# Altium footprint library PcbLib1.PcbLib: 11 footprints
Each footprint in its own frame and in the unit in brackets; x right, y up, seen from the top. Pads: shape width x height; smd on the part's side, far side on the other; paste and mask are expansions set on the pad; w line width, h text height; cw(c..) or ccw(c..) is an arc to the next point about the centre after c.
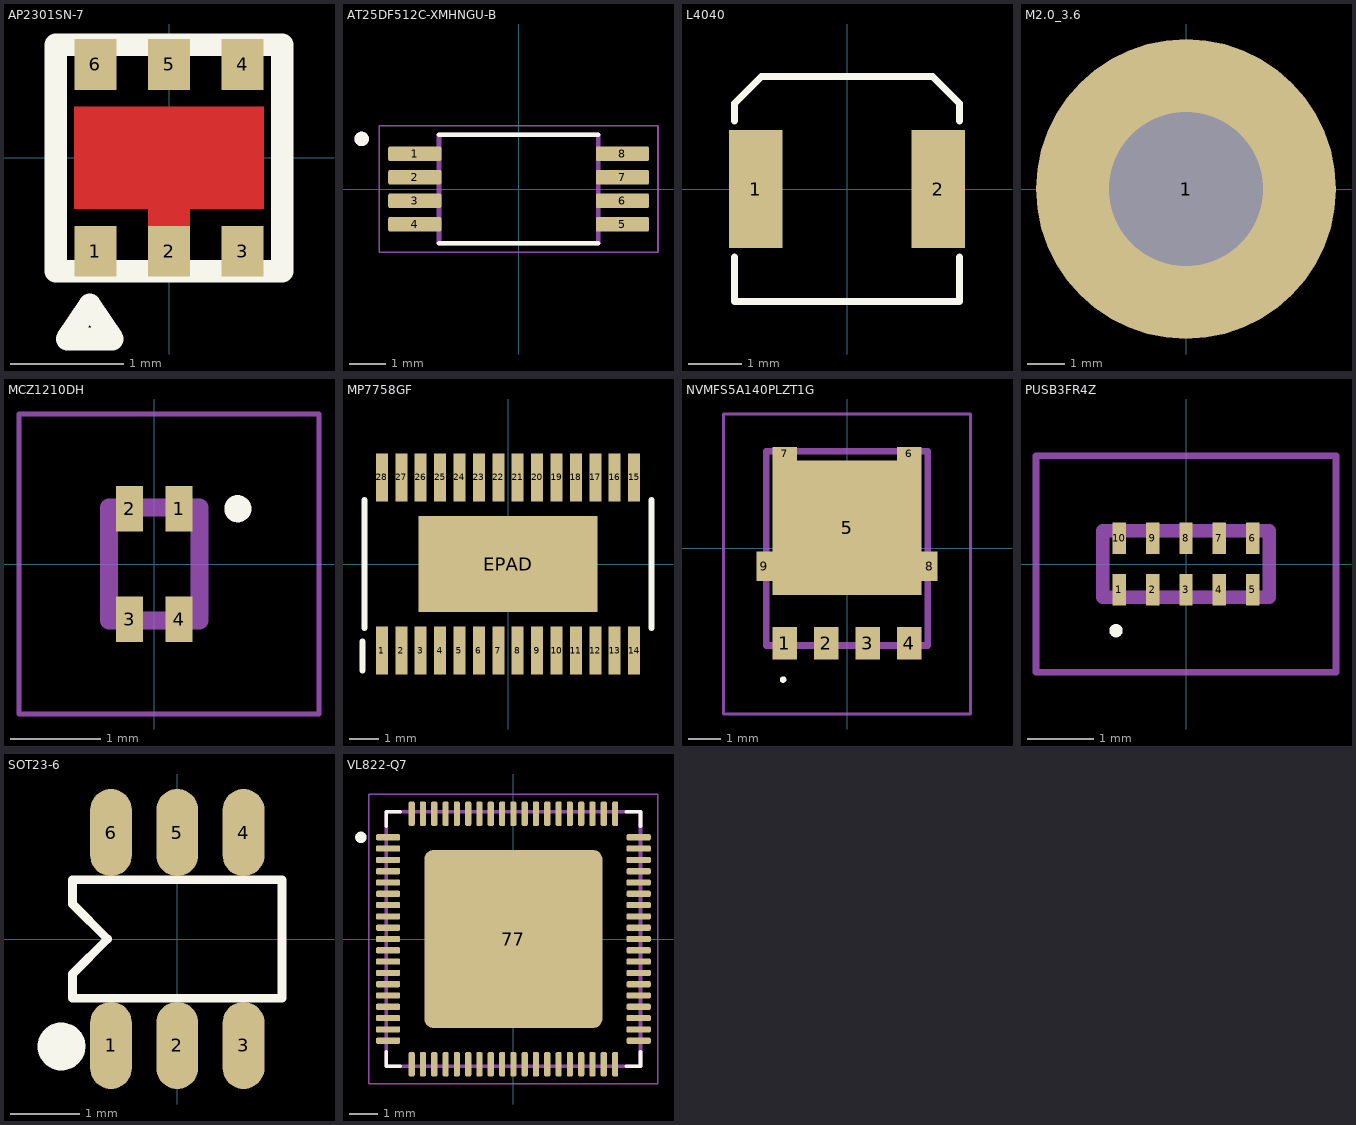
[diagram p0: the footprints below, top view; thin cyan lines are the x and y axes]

## AP2301SN-7 [mm] "Power Switch ICs - Power Distribution 2.0A SGL CH 70mOhm 2.5A 2.7 to 5.5V"
pads (6):
  rect 0.37x0.45 smd: 1(-0.65,-0.825) 2(0,-0.825) 3(0.65,-0.825) 4(0.65,0.825) 5(0,0.825) 6(-0.65,0.825)
Top Layer:
  region: -0.835,0.45 -0.835,-0.45 -0.185,-0.45 -0.185,-0.825 0.185,-0.825 0.185,-0.45 0.835,-0.45 0.835,0.45
Top Overlay:
  lines w0.2: -1,-1 -1,1 1,1 1,-1 -1,-1 ; -0.9,-1.6 -0.7,-1.3 -0.5,-1.6 -0.9,-1.6
3D body "U-DFN2020-6.stp": height 0.61, standoff 0.01, extent -1,-1 1,1

## AT25DF512C-XMHNGU-B [mm] "NOR Flash 512Kb, 1.65V, 85Mhz Serial Flash"
pads (8):
  rrect25% 1.47x0.41 smd: 1(-2.87,0.975) 2(-2.87,0.325) 3(-2.87,-0.325) 4(-2.87,-0.975) 5(2.87,-0.975) 6(2.87,-0.325) 7(2.87,0.325) 8(2.87,0.975)
Top Overlay:
  circle w0.2: c-4.34,1.385 r0.1
  lines w0.127: -2.2,-1.5 2.2,-1.5 ; -2.2,1.5 2.2,1.5
Mechanical 13:
  circle w0.2: c-4.34,1.385 r0.1
  lines w0.127: -2.2,-1.5 -2.2,1.5 2.2,1.5 2.2,-1.5 -2.2,-1.5
Mechanical 15:
  lines w0.05: -3.855,-1.75 -3.855,1.75 3.855,1.75 3.855,-1.75 -3.855,-1.75
3D body "step_temp.STEP": height 1.2, standoff 0, extent -3.2,-1.5 3.2,1.5

## L4040 [mm]
height 2.108
pads (2):
  rect 1x2.2 smd: 1(-1.7,0) 2(1.7,0)
Top Overlay:
  lines w0.127: -2.1,-1.27 -2.1,-2.1 2.1,-2.1 2.1,-1.27 ; -2.1,1.27 -2.1,1.6 -1.6,2.1 1.6,2.1 2.1,1.6 2.1,1.27
Top Assembly:
  text "L2" at 0.444,0.374 h0.64
3D body "L_XND4040TK.STEP": height 1.8, standoff 0, extent -2,-2 2,2

## M2.0_3.6 [mm]
pads (1):
  round 8 hole 4.1: 1(0,0)

## MCZ1210DH [mm]
pads (4):
  rect 0.3x0.5 smd: 1(0.275,0.613) 2(-0.275,0.613) 3(-0.275,-0.613) 4(0.275,-0.613)
Top Overlay:
  circle w0.2: c0.925,0.613 r0.05
Mechanical 13:
  lines w0.2: -0.5,-0.625 -0.5,0.625 0.5,0.625 0.5,-0.625 -0.5,-0.625
Mechanical 15:
  lines w0.05: -1.5,-1.663 -1.5,1.663 1.825,1.663 1.825,-1.663 -1.5,-1.663
3D body "MCZ1210DH500L2TA0G.stp": height 0.7, standoff 0, extent -0.5,-0.833 0.5,0.833

## MP7758GF [mm] "TSSOP-28"
pads (29):
  rect 0.4x1.6 smd: 1(-4.225,-2.9) 2(-3.575,-2.9) 3(-2.925,-2.9) 4(-2.275,-2.9) 5(-1.625,-2.9) 6(-0.975,-2.9) 7(-0.325,-2.9) 8(0.325,-2.9) 9(0.975,-2.9) 10(1.625,-2.9) 11(2.275,-2.9) 12(2.925,-2.9) 13(3.575,-2.9) 14(4.225,-2.9) 15(4.225,2.9) 16(3.575,2.9) 17(2.925,2.9) 18(2.275,2.9) 19(1.625,2.9) 20(0.975,2.9) 21(0.325,2.9) 22(-0.325,2.9) 23(-0.975,2.9) 24(-1.625,2.9) 25(-2.275,2.9) 26(-2.925,2.9) 27(-3.575,2.9) 28(-4.225,2.9)
  rect 6x3.2 smd: EPAD(0,0)
Top Overlay:
  lines w0.2: -4.875,-3.575 -4.875,-2.6 ; -4.8,-2.15 -4.8,2.15 ; 4.8,-2.15 4.8,2.15
3D body "PW0028A.stp": height 1.13, standoff 0, extent -4.85,-3.2 4.85,3.2

## NVMFS5A140PLZT1G [mm]
pads (9):
  rect 0.75x1 smd: 1(-1.905,-2.89) 2(-0.635,-2.89) 3(0.635,-2.89) 4(1.905,-2.89)
  rect 4.56x4.105 smd: 5(0,0.628)
  rect 0.75x0.425 smd: 6(1.905,2.89) 7(-1.905,2.89)
  rect 0.495x0.905 smd: 8(2.52,-0.547) 9(-2.52,-0.547)
Top Overlay:
  lines w0.1: -2,-4 cw(c-1.95,-4) -1.9,-4 cw(c-1.95,-4) -2,-4
Mechanical 13:
  lines w0.2: -2.46,-2.96 -2.46,2.96 2.46,2.96 2.46,-2.96 -2.46,-2.96
Mechanical 15:
  lines w0.1: -3.768,-5.05 -3.768,4.103 3.768,4.103 3.768,-5.05 -3.768,-5.05
3D body "NVMFS5A140PLZT1G.stp": height 1.2, standoff 0, extent -2.718,-3.315 2.718,3.06

## PCBComponent_1 [mm]

## PUSB3FR4Z [mm]
pads (10):
  rect 0.2x0.475 smd: 1(-1,-0.388) 2(-0.5,-0.388) 3(0,-0.388) 4(0.5,-0.388) 5(1,-0.388) 6(1,0.388) 7(0.5,0.388) 8(0,0.388) 9(-0.5,0.388) 10(-1,0.388)
Top Overlay:
  lines w0.1: -1.1,-1 ccw(c-1.05,-1) -1,-1 ccw(c-1.05,-1) -1.1,-1
Mechanical 13:
  lines w0.2: -1.25,-0.5 -1.25,0.5 1.25,0.5 1.25,-0.5 -1.25,-0.5
Mechanical 15:
  lines w0.1: -2.25,-1.625 -2.25,1.625 2.25,1.625 2.25,-1.625 -2.25,-1.625
3D body "PUSB3FA2Z.stp": height 0.6, standoff 0, extent -1.25,-0.606 1.25,0.606

## SOT23-6 [mm]
pads (6):
  oval 0.599x1.25 smd: 1(-0.95,-1.525) 2(0,-1.525) 3(0.95,-1.525) 4(0.95,1.525) 5(0,1.525) 6(-0.95,1.525)
Top Overlay:
  circle w0.381: c-1.66,-1.54 r0.152
  lines w0.127: -1.5,-0.85 -1.5,-0.5 -1,0 -1.5,0.5 -1.5,0.85 1.5,0.85 1.5,-0.85 -1.5,-0.85
3D body "sot-23-6.stp": height 1.05, standoff -0.06, extent -1.46,-1.422 1.46,1.422

## VL822-Q7 [mm] "USB 3.2 Gen 2x1  4-Port Hub Controller"
pads (77):
  rrect50% 0.86x0.22 smd: 1(-4.435,3.6) 2(-4.435,3.2) 3(-4.435,2.8) 4(-4.435,2.4) 5(-4.435,2) 6(-4.435,1.6) 7(-4.435,1.2) 8(-4.435,0.8) 9(-4.435,0.4) 10(-4.435,0) 11(-4.435,-0.4) 12(-4.435,-0.8) 13(-4.435,-1.2) 14(-4.435,-1.6) 15(-4.435,-2) 16(-4.435,-2.4) 17(-4.435,-2.8) 18(-4.435,-3.2) 19(-4.435,-3.6) 39(4.435,-3.6) 40(4.435,-3.2) 41(4.435,-2.8) 42(4.435,-2.4) 43(4.435,-2) 44(4.435,-1.6) 45(4.435,-1.2) 46(4.435,-0.8) 47(4.435,-0.4) 48(4.435,0) 49(4.435,0.4) 50(4.435,0.8) 51(4.435,1.2) 52(4.435,1.6) 53(4.435,2) 54(4.435,2.4) 55(4.435,2.8) 56(4.435,3.2) 57(4.435,3.6)
  rrect50% 0.22x0.86 smd: 20(-3.6,-4.435) 21(-3.2,-4.435) 22(-2.8,-4.435) 23(-2.4,-4.435) 24(-2,-4.435) 25(-1.6,-4.435) 26(-1.2,-4.435) 27(-0.8,-4.435) 28(-0.4,-4.435) 29(0,-4.435) 30(0.4,-4.435) 31(0.8,-4.435) 32(1.2,-4.435) 33(1.6,-4.435) 34(2,-4.435) 35(2.4,-4.435) 36(2.8,-4.435) 37(3.2,-4.435) 38(3.6,-4.435) 58(3.6,4.435) 59(3.2,4.435) 60(2.8,4.435) 61(2.4,4.435) 62(2,4.435) 63(1.6,4.435) 64(1.2,4.435) 65(0.8,4.435) 66(0.4,4.435) 67(0,4.435) 68(-0.4,4.435) 69(-0.8,4.435) 70(-1.2,4.435) 71(-1.6,4.435) 72(-2,4.435) 73(-2.4,4.435) 74(-2.8,4.435) 75(-3.2,4.435) 76(-3.6,4.435)
  rrect10% 6.3x6.3 smd: 77(0,0)
Top Overlay:
  circle w0.2: c-5.4,3.6 r0.1
  lines w0.127: -4.5,-4 -4.5,-4.5 -4,-4.5 ; -4.5,4 -4.5,4.5 -4,4.5 ; 4,-4.5 4.5,-4.5 4.5,-4 ; 4,4.5 4.5,4.5 4.5,4
Top Paste:
  region: 0.675,-0.756 -0.676,-0.756 -0.676,0.755 0.675,0.755
  region: -1.265,-0.756 -2.619,-0.756 -2.619,0.755 -1.265,0.755
  region: 2.615,-0.755 1.266,-0.755 1.266,0.755 2.615,0.755
  region: -1.265,1.348 -2.62,1.348 -2.62,2.855 -1.265,2.855
  region: 0.675,1.347 -0.676,1.347 -0.676,2.855 0.675,2.855
  region: 2.615,1.347 1.267,1.347 1.267,2.855 2.615,2.855
  region: -1.265,-2.858 -2.618,-2.858 -2.618,-1.345 -1.265,-1.345
  region: 0.675,-2.857 -0.675,-2.857 -0.675,-1.345 0.675,-1.345
  region: 2.615,-2.858 1.266,-2.858 1.266,-1.345 2.615,-1.345
Mechanical 13:
  lines w0.127: -4.5,-4.5 -4.5,4.5 4.5,4.5 4.5,-4.5 -4.5,-4.5
Mechanical 15:
  lines w0.05: -5.12,-5.12 -5.12,5.12 5.12,5.12 5.12,-5.12 -5.12,-5.12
